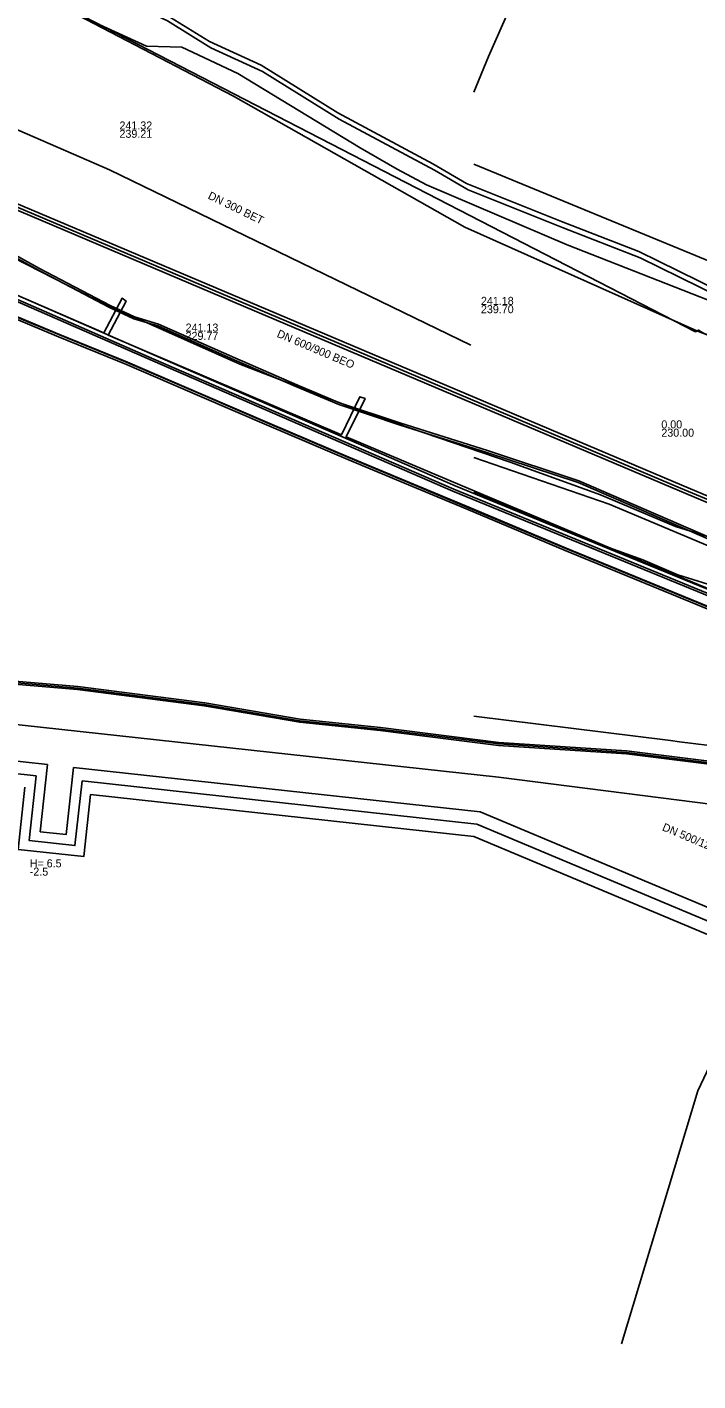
# Model space of a CAD drawing. Extents: x -596024 to -594475, y -1163820 to -1161957.
# Drawn here: x -595044.6 to -594977.6, y -1162194.5 to -1162059.2 of the extents above; entities that cross this region are included whole.
import ezdxf

# ---------------------------------------------------------------- set-up
doc = ezdxf.new("R2010")
doc.units = 0
for name, color, linetype in [('Vrstva 1', 7, 'Continuous'), ('Vrstva 10', 7, 'Continuous'), ('Vrstva 12', 7, 'Continuous'), ('Vrstva 19', 7, 'Continuous'), ('Vrstva 29', 7, 'Continuous'), ('Vrstva 30', 7, 'Continuous'), ('Vrstva 32', 7, 'Continuous'), ('Vrstva 4', 7, 'Continuous'), ('Vrstva 42', 7, 'Continuous'), ('Vrstva 44', 7, 'Continuous'), ('Vrstva 53', 7, 'Continuous'), ('Vrstva 55', 7, 'Continuous'), ('Vrstva 58', 7, 'Continuous'), ('Vrstva 9', 7, 'Continuous')]:
    doc.layers.add(name, color=color, linetype=linetype)

msp = doc.modelspace()

# ---------------------------------------------------------------- linework, layer by layer
at = {"layer": 'Vrstva 1'}
for p, q in [((-595036.41, -1162073.46), (-595083.06, -1162053.24)), ((-595000.28, -1162090.99), (-595036.41, -1162073.46))]:
    msp.add_line(p, q, dxfattribs=at)
at = {"layer": 'Vrstva 10'}
for p, q in [((-595021.677, -1162087.656), (-595084.987, -1162060.836)), ((-595021.443, -1162087.104), (-595084.753, -1162060.284)), ((-594979.436, -1162105.539), (-595021.677, -1162087.656)), ((-595021.443, -1162087.104), (-594979.202, -1162104.986)), ((-594940.467, -1162122.036), (-594979.436, -1162105.539)), ((-594979.202, -1162104.986), (-594940.233, -1162121.484))]:
    msp.add_line(p, q, dxfattribs=at)
at = {"layer": 'Vrstva 12'}
for points in [[(-595000, -1162065.69), (-594998.51, -1162062.14), (-594995.6, -1162055.46), (-594995.3, -1162055.07), (-594993.95, -1162051.82), (-594990.98, -1162044.74), (-594990.82, -1162043.64), (-594990.5, -1162042.68), (-594989.91, -1162041.29)], [(-594884.92, -1162121.76), (-594911.54, -1162110.55), (-594949.23, -1162093.8), (-595000, -1162072.9)], [(-595000, -1162102.21), (-594986.48, -1162106.88), (-594968, -1162114.63), (-594949.73, -1162122.77), (-594931.56, -1162129.92)], [(-595000, -1162105.69), (-594988.08, -1162110.65), (-594983.09, -1162112.45)], [(-594983.09, -1162112.45), (-594979.59, -1162113.93)], [(-594979.59, -1162113.93), (-594969.11, -1162117.2), (-594950.59, -1162124.75), (-594943.32, -1162126.88)], [(-594980.35, -1162130.49), (-595000, -1162128.06)], [(-594979.44, -1162130.61), (-594980.35, -1162130.49)], [(-594970.72, -1162131.69), (-594979.44, -1162130.61)]]:
    msp.add_lwpolyline(points, dxfattribs=at)
at = {"layer": 'Vrstva 19'}
for points in [[(-594834.13, -1162150.42), (-594853.67, -1162141.96), (-594867.94, -1162135.71), (-594883.53, -1162129.07), (-594901.79, -1162120.42), (-594926.81, -1162110.23), (-594928.91, -1162111.02), (-594933.4, -1162109.17), (-594934.76, -1162108.55), (-594938.6, -1162106.86), (-594959.6, -1162097.43), (-594961.01, -1162092.97), (-594963.04, -1162092.01), (-594974.93, -1162087.13), (-594990.65, -1162080.96), (-595004.73, -1162074.95), (-595007.66, -1162073.38), (-595011.36, -1162071.28), (-595023.59, -1162063.83), (-595029.17, -1162061.22), (-595032.7, -1162061.12), (-595041.37, -1162057.15), (-595042.54, -1162053.99), (-595047.79, -1162051.63)], [(-595230.98, -1162092.97), (-595220.85, -1162096.4), (-595168.86, -1162107.75), (-595081.2, -1162125.02), (-594997.53, -1162134.17), (-594961.69, -1162138.72), (-594953.62, -1162140.15), (-594950.84, -1162140.46)]]:
    msp.add_lwpolyline(points, dxfattribs=at)
at = {"layer": 'Vrstva 29'}
for points in [[(-595043.726, -1162134.03), (-595084.185, -1162129.598), (-595148.279, -1162115.16)], [(-595039.153, -1162134.53), (-595039.861, -1162140.991), (-595044.434, -1162140.49), (-595043.726, -1162134.03)], [(-594941.776, -1162163.139), (-594999.69, -1162138.853), (-595039.153, -1162134.53)]]:
    msp.add_lwpolyline(points, dxfattribs=at)
at = {"layer": 'Vrstva 30'}
for points in [[(-595042.596, -1162132.896), (-595083.979, -1162128.363), (-595148.98, -1162113.721)], [(-595040.011, -1162133.178), (-595040.746, -1162139.888), (-595043.331, -1162139.605), (-595042.596, -1162132.896)], [(-594942.214, -1162161.6), (-594999.374, -1162137.63), (-595040.011, -1162133.178)], [(-595038.295, -1162135.882), (-595038.976, -1162142.094), (-595045.537, -1162141.375), (-595044.856, -1162135.164)], [(-594941.337, -1162164.679), (-595000.006, -1162140.076), (-595038.295, -1162135.882)]]:
    msp.add_lwpolyline(points, dxfattribs=at)
at = {"layer": 'Vrstva 42'}
for points in [[(-595076.85, -1162071.09), (-595070.609, -1162071.252), (-595067.572, -1162072.08), (-595066.504, -1162072.834), (-595064.969, -1162072.729), (-595057.526, -1162075.848), (-595046.042, -1162082.224), (-595037.826, -1162086.437), (-595033.97, -1162088.19), (-595033.845, -1162088.227), (-595023.376, -1162092.878), (-595010.628, -1162097.806), (-594996.365, -1162102.687), (-594987.338, -1162105.952), (-594979.828, -1162109.103), (-594975.585, -1162110.428), (-594962.839, -1162116.145), (-594952.248, -1162121.006), (-594946.053, -1162123.832), (-594934.8, -1162128.336), (-594926.951, -1162132.009), (-594926.08, -1162134.217), (-594922.779, -1162135.588), (-594916.95, -1162137.709)], [(-594972.11, -1162112.058), (-594980.58, -1162108.398), (-594989.484, -1162104.536), (-594998.639, -1162101.505), (-595007.279, -1162098.775), (-595013.425, -1162096.736), (-595017.691, -1162094.938), (-595023.87, -1162092.258), (-595031.495, -1162088.876), (-595033.894, -1162088.156), (-595036.326, -1162087.03), (-595043.393, -1162083.322), (-595049.15, -1162080.173)], [(-595049.25, -1162080.347), (-595043.487, -1162083.498), (-595036.414, -1162087.21), (-595033.966, -1162088.344), (-595031.565, -1162089.064), (-595023.95, -1162092.442), (-595017.769, -1162095.122), (-595013.495, -1162096.924), (-595007.341, -1162098.965), (-594998.701, -1162101.695), (-594989.556, -1162104.724), (-594980.66, -1162108.582), (-594972.19, -1162112.242)], [(-595050.25, -1162124.49), (-595039.596, -1162125.409), (-595026.932, -1162127.038), (-595017.39, -1162128.669), (-595009.367, -1162129.499), (-594997.514, -1162130.979), (-594984.744, -1162131.839), (-594968.747, -1162133.829), (-594955.433, -1162135.149), (-594946.986, -1162135.809), (-594942.51, -1162136.43), (-594937.641, -1162136.39), (-594933.514, -1162135.941), (-594928.427, -1162136.761), (-594924.123, -1162136.5), (-594919.817, -1162136.951), (-594917.127, -1162136.548), (-594914.857, -1162136.19), (-594913.634, -1162136.17)], [(-594968.73, -1162133.68), (-594984.73, -1162131.69), (-594997.5, -1162130.83), (-595009.35, -1162129.35), (-595017.37, -1162128.52), (-595026.91, -1162126.89), (-595039.58, -1162125.26), (-595050.24, -1162124.34)], [(-595050.23, -1162124.19), (-595039.564, -1162125.111), (-595026.888, -1162126.742), (-595017.35, -1162128.371), (-595009.333, -1162129.201), (-594997.486, -1162130.681), (-594984.716, -1162131.541), (-594968.713, -1162133.531)]]:
    msp.add_lwpolyline(points, dxfattribs=at)
at = {"layer": 'Vrstva 44'}
for points in [[(-594935.512, -1162102.262), (-594940.59, -1162099.98), (-594954.64, -1162093.85), (-594962.23, -1162090.66), (-594975.58, -1162085.52), (-594983.51, -1162081.62), (-594991.22, -1162078.62), (-595000.71, -1162074.83), (-595004.08, -1162072.86), (-595013.58, -1162067.77), (-595021.25, -1162063.01), (-595026.41, -1162060.65), (-595030.74, -1162057.96), (-595035.38, -1162055.75), (-595043.63, -1162052), (-595048.55, -1162050.23)], [(-595066.105, -1162080.68), (-595062.648, -1162081.161), (-595060.545, -1162081.694), (-595054.166, -1162084.398), (-595048.287, -1162087.117), (-595041.419, -1162089.957), (-595034.638, -1162092.727), (-595027.287, -1162095.887), (-595020.408, -1162098.857), (-595012.508, -1162102.227), (-595006.858, -1162104.577), (-595000.518, -1162107.237), (-594990.789, -1162111.317), (-594975.868, -1162117.447), (-594966.828, -1162121.287), (-594957.228, -1162125.287), (-594950.556, -1162128.178), (-594946.028, -1162130.341), (-594943.328, -1162132.061), (-594935.876, -1162135.638), (-594926.073, -1162139.775), (-594923.737, -1162140.504), (-594923.306, -1162140.637), (-594922.193, -1162141.292)], [(-595048.367, -1162087.301), (-595041.495, -1162090.141), (-595034.716, -1162092.911), (-595027.367, -1162096.071), (-595020.486, -1162099.041), (-595012.586, -1162102.411), (-595006.936, -1162104.761), (-595000.596, -1162107.421), (-594990.865, -1162111.501), (-594975.946, -1162117.631), (-594966.906, -1162121.471), (-594957.306, -1162125.471), (-594950.638, -1162128.36), (-594946.126, -1162130.517), (-594943.426, -1162132.237), (-594935.958, -1162135.82), (-594926.141, -1162139.963), (-594923.797, -1162140.694)]]:
    msp.add_lwpolyline(points, dxfattribs=at)
at = {"layer": 'Vrstva 53'}
msp.add_lwpolyline([(-594878.712, -1161956.88), (-594977.6, -1162165.5), (-594985.247, -1162190.772)], dxfattribs=at)
at = {"layer": 'Vrstva 55'}
for points in [[(-595280.847, -1161956.88), (-595167.74, -1162005.1), (-595152.57, -1162008.28), (-595132.46, -1162013.93), (-595105.64, -1162029.1), (-595096.82, -1162031.08), (-595083.7, -1162037.44), (-595044.35, -1162055.33), (-594977.82, -1162089.64)], [(-595058.73, -1162080.33), (-595036.98, -1162089.76), (-595035.15, -1162086.29), (-595034.75, -1162086.58), (-595036.55, -1162089.98), (-595013.23, -1162099.96), (-595011.37, -1162096.14), (-595010.86, -1162096.32), (-595012.76, -1162100.14), (-594998.4, -1162106.21), (-594982.82, -1162112.73), (-594967.44, -1162119.08), (-594968.17, -1162113.18), (-594967.54, -1162111.09)], [(-594977.82, -1162089.64), (-594977.55, -1162089.48), (-594977.09, -1162089.76), (-594973.44, -1162091.455), (-594970.02, -1162092.96), (-594963.54, -1162096.55), (-594962.02, -1162097.76), (-594961.22, -1162098.05), (-594958.93, -1162097.72), (-594958.44, -1162097.55), (-594956.98, -1162097.68), (-594956.44, -1162097.68), (-594940.04, -1162105), (-594938.58, -1162105.42), (-594938.34, -1162105.42), (-594937.57, -1162105.65), (-594937.33, -1162105.61), (-594937.04, -1162105.51)]]:
    msp.add_lwpolyline(points, dxfattribs=at)
at = {"layer": 'Vrstva 58'}
for points in [[(-595070.082, -1162044.552), (-595044.512, -1162055.396), (-595024.001, -1162066.113), (-595000.874, -1162079.189), (-594977.696, -1162089.547), (-594937.648, -1162105.187), (-594907.394, -1162121.391), (-594889.549, -1162128.57), (-594872.678, -1162139.852), (-594855.521, -1162146.975), (-594837.445, -1162154.525)], [(-595048.408, -1162050.859), (-595043.488, -1162052.629), (-595035.238, -1162056.379), (-595030.598, -1162058.589), (-595026.268, -1162061.279), (-595021.108, -1162063.639), (-595013.438, -1162068.399), (-595003.938, -1162073.489), (-595000.568, -1162075.459), (-594991.078, -1162079.249), (-594983.368, -1162082.249), (-594975.438, -1162086.149), (-594962.088, -1162091.289), (-594954.498, -1162094.479), (-594940.448, -1162100.609), (-594931.311, -1162104.727), (-594928.375, -1162106.017), (-594910.192, -1162110.138), (-594905.126, -1162111.489), (-594901.365, -1162110.121), (-594899.057, -1162111.147), (-594898.67, -1162111.91)], [(-594941.094, -1162198.987), (-594920.43, -1162143.658), (-594919.617, -1162140.938), (-594919.37, -1162139.932), (-594919.014, -1162139.223), (-594918.681, -1162138.689), (-594919.617, -1162138.478), (-594921.764, -1162138.03), (-594934.783, -1162132.453), (-594952.315, -1162124.916), (-594967.814, -1162119.636), (-595002.082, -1162105.573), (-595032.074, -1162092.561), (-595055.072, -1162082.532)], [(-594917.46, -1162138.59), (-594918.145, -1162138.56), (-594921.7, -1162137.83), (-594934.7, -1162132.26), (-594952.24, -1162124.72), (-594967.74, -1162119.44), (-595002, -1162105.38), (-595031.99, -1162092.37), (-595054.99, -1162082.34)], [(-594917.46, -1162138.59), (-594918.145, -1162138.56), (-594921.7, -1162137.83), (-594934.7, -1162132.26), (-594952.24, -1162124.72), (-594967.74, -1162119.44), (-595002, -1162105.38), (-595031.99, -1162092.37), (-595054.99, -1162082.34)], [(-594919.368, -1162137.929), (-594921.585, -1162137.464), (-594934.55, -1162131.91), (-594952.103, -1162124.364), (-594967.606, -1162119.083), (-595001.852, -1162105.029), (-595031.838, -1162092.02), (-595054.841, -1162081.989)], [(-595048.267, -1162087.069), (-595041.397, -1162089.909)], [(-595041.397, -1162089.909), (-595034.617, -1162092.679), (-595027.267, -1162095.839), (-595020.387, -1162098.809), (-595012.487, -1162102.179), (-595006.837, -1162104.529), (-595000.497, -1162107.189), (-594990.767, -1162111.269), (-594975.847, -1162117.399), (-594966.807, -1162121.239), (-594957.207, -1162125.239), (-594950.537, -1162128.129), (-594946.007, -1162130.299), (-594943.307, -1162132.019), (-594935.857, -1162135.589), (-594926.057, -1162139.729), (-594922.857, -1162140.779), (-594922.177, -1162141.239), (-594919.817, -1162141.829), (-594919.607, -1162143.459), (-594919.657, -1162143.929), (-594926.607, -1162162.569), (-594933.427, -1162180.919), (-594940.387, -1162199.549)]]:
    msp.add_lwpolyline(points, dxfattribs=at)
at = {"layer": 'Vrstva 9'}
for p, q in [((-595021.56, -1162087.38), (-595084.87, -1162060.56)), ((-594979.319, -1162105.262), (-595021.56, -1162087.38)), ((-594940.35, -1162121.76), (-594979.319, -1162105.262))]:
    msp.add_line(p, q, dxfattribs=at)

# ---------------------------------------------------------------- texts
at = {"layer": 'Vrstva 12'}
for s, p in [('241.13', (-595028.8, -1162089.628)), ('229.77', (-595028.8, -1162090.46)), ('0.00', (-594981.249, -1162099.301)), ('230.00', (-594981.249, -1162100.133))]:
    msp.add_text(s, height=0.8, dxfattribs=at).set_placement(p)
msp.add_text('DN 600/900 BEO', height=0.8, rotation=337.05478, dxfattribs=at).set_placement((-595019.743, -1162090.136))
at = {"layer": 'Vrstva 32'}
msp.add_text('DN 500/125   165/ 120', height=0.8, rotation=337.24296, dxfattribs=at).set_placement((-594981.23, -1162139.451))
for s, p in [('H= 6.5  ', (-595044.378, -1162143.169)), ('-2.5', (-595044.378, -1162144.001))]:
    msp.add_text(s, height=0.8, dxfattribs=at).set_placement(p)
at = {"layer": 'Vrstva 4'}
for s, p in [('241.32', (-595035.41, -1162069.428)), ('239.21', (-595035.41, -1162070.26)), ('241.18', (-594999.28, -1162086.958)), ('239.70', (-594999.28, -1162087.79))]:
    msp.add_text(s, height=0.8, dxfattribs=at).set_placement(p)
msp.add_text('DN 300 BET', height=0.8, rotation=334.09169, dxfattribs=at).set_placement((-595026.635, -1162076.313))

doc.saveas('drawing.dxf')
